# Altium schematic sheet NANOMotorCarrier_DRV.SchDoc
size A3
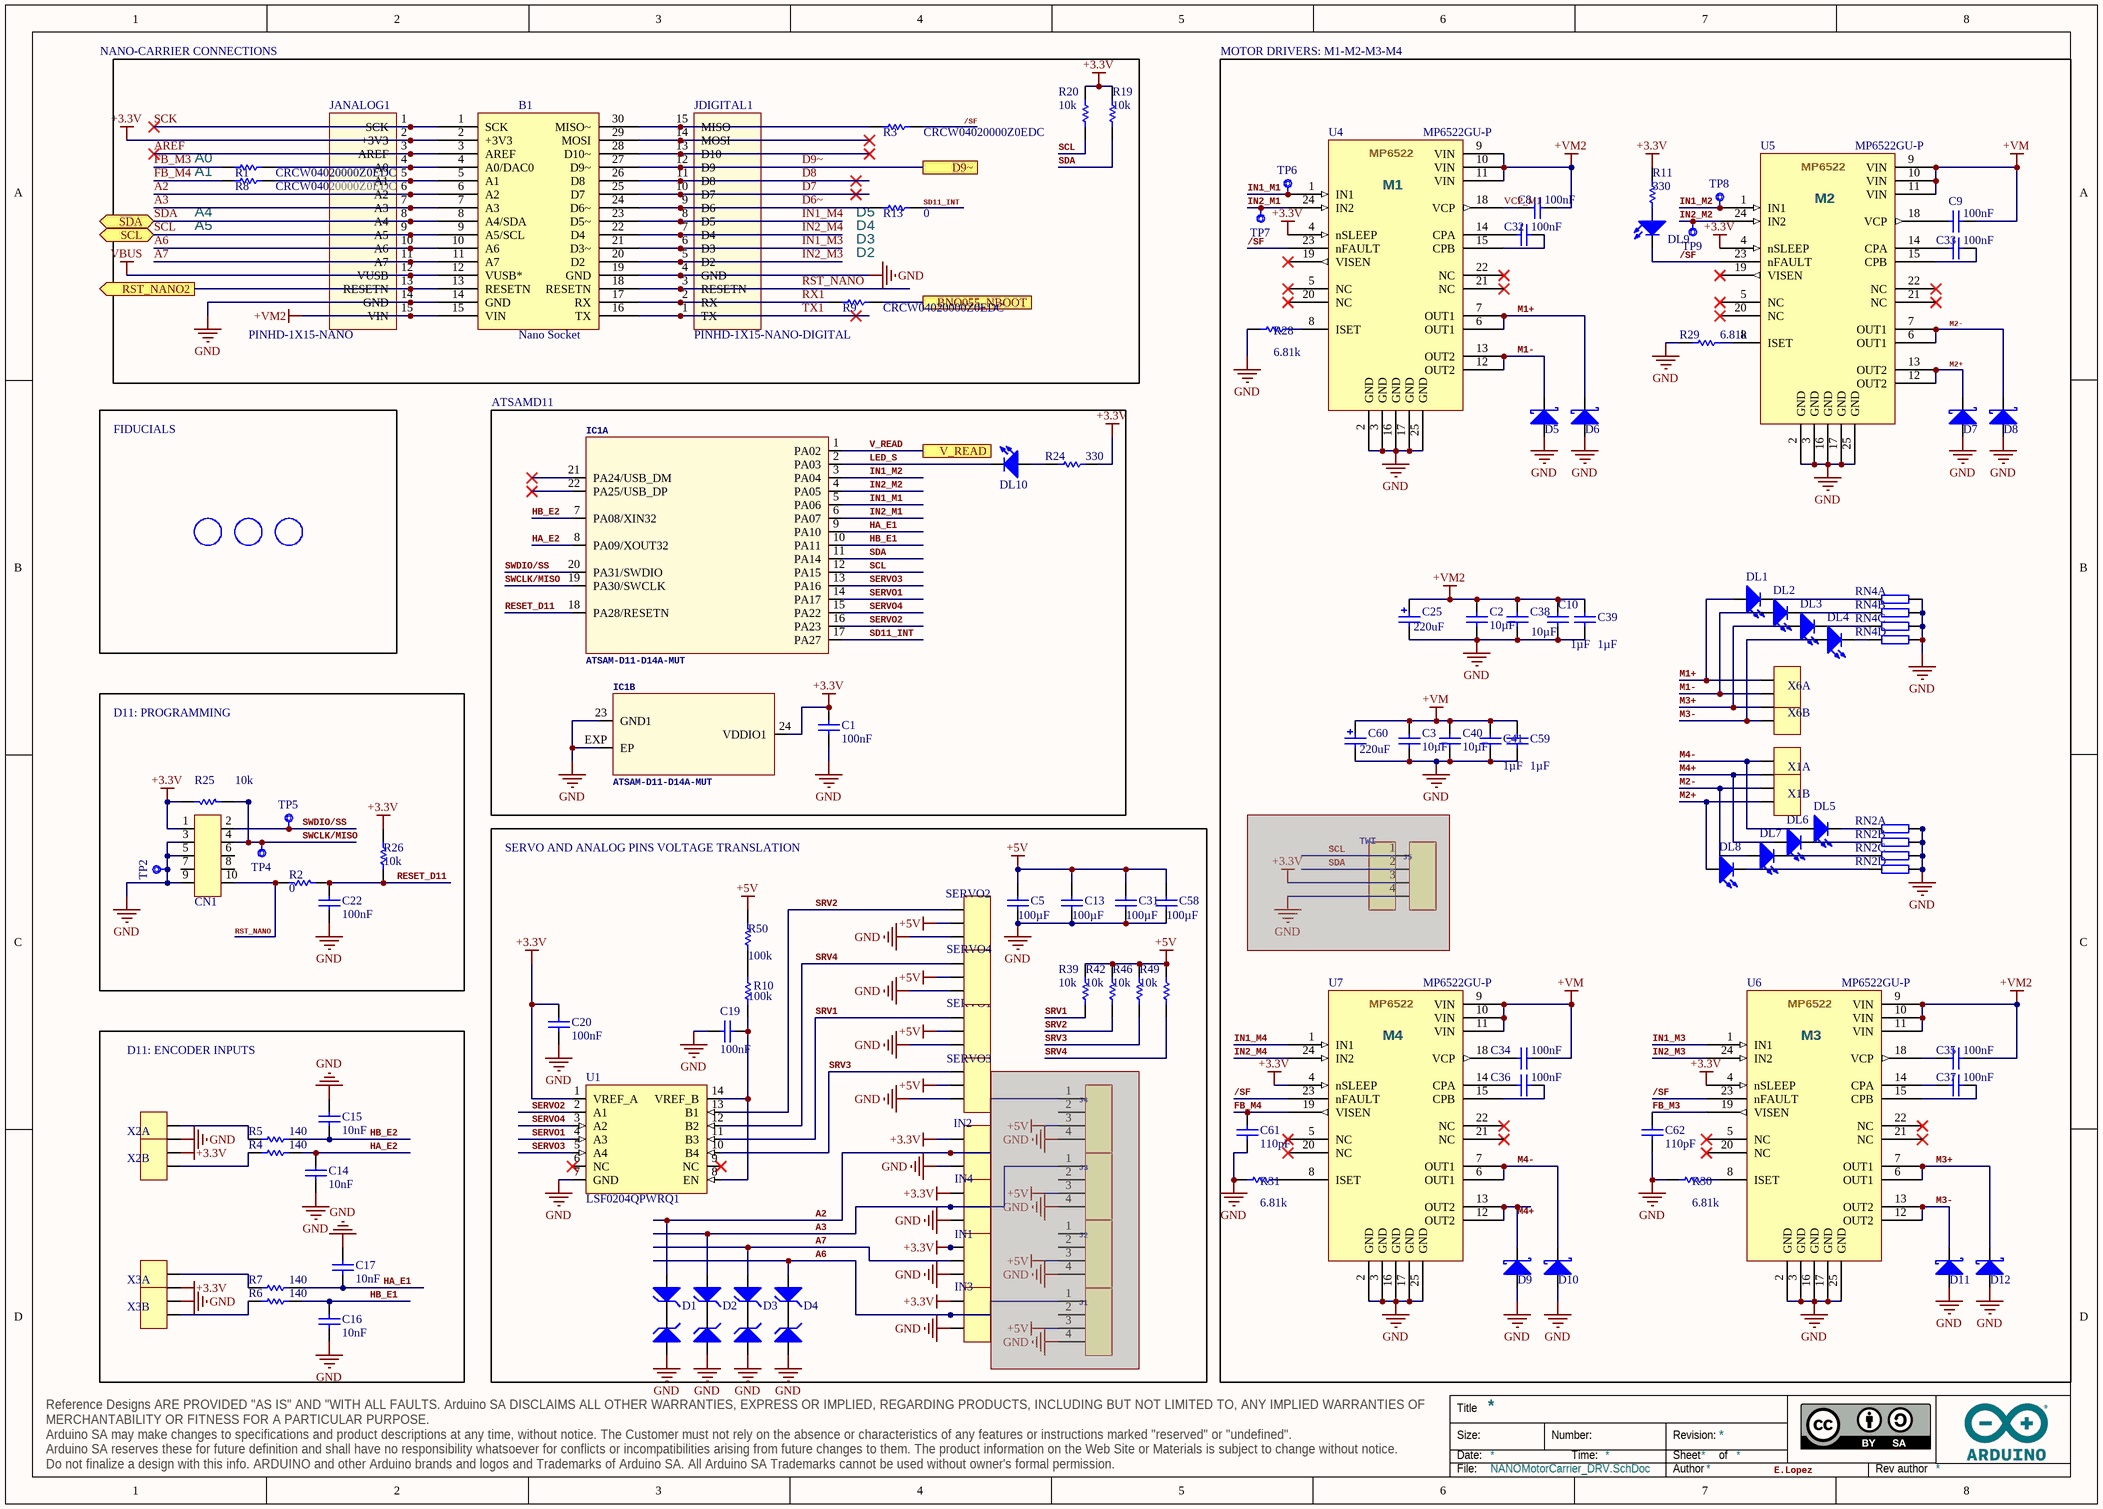
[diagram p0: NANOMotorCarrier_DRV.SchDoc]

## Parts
B1  Nano Socket  [Nano Socket-Footprint-1]
C1  value 100nF  [CAP-0402]  (hidden comment: GRM155R61H104KE19D)
C2  value 10µF  [CAP-1206]  (hidden comment: GRM31CR61H106KA12L)
C3  value 10µF  [CAP-1206]  (hidden comment: GRM31CR61H106KA12L)
C5  value 100µF  [CAP-1206]  (hidden comment: CL31A107MPHNNNE)
C8  value 100nF  [CAP-0402]  (hidden comment: GRM155R61H104KE19D)
C9  value 100nF  [CAP-0402]  (hidden comment: GRM155R61H104KE19D)
C10  value 1µF  [CAP-0603]  (hidden comment: C0603C105K3PACTU)
C13  value 100µF  [CAP-1206]  (hidden comment: CL31A107MPHNNNE)
C14  value 10nF  [CAP-0402]  (hidden comment: C0402C103K5RACTU)
C15  value 10nF  [CAP-0402]  (hidden comment: C0402C103K5RACTU)
C16  value 10nF  [CAP-0402]  (hidden comment: C0402C103K5RACTU)
C17  value 10nF  [CAP-0402]  (hidden comment: C0402C103K5RACTU)
C19  value 100nF  [CAP-0402]  (hidden comment: GRM155R61H104KE19D)
C20  value 100nF  [CAP-0402]  (hidden comment: GRM155R61H104KE19D)
C22  value 100nF  [CAP-0402]  (hidden comment: GRM155R61H104KE19D)
C25  Capacitance: 220uF  [CAPAE7866X80L]  (hidden comment: EEEFTE221XAP)
C31  value 100µF  [CAP-1206]  (hidden comment: CL31A107MPHNNNE)
C32  value 100nF  [CAP-0402]  (hidden comment: GRM155R61H104KE19D)
C33  value 100nF  [CAP-0402]  (hidden comment: GRM155R61H104KE19D)
C34  value 100nF  [CAP-0402]  (hidden comment: GRM155R61H104KE19D)
C35  value 100nF  [CAP-0402]  (hidden comment: GRM155R61H104KE19D)
C36  value 100nF  [CAP-0402]  (hidden comment: GRM155R61H104KE19D)
C37  value 100nF  [CAP-0402]  (hidden comment: GRM155R61H104KE19D)
C38  value 10µF  [CAP-1206]  (hidden comment: GRM31CR61H106KA12L)
C39  value 1µF  [CAP-0603]  (hidden comment: C0603C105K3PACTU)
C40  value 10µF  [CAP-1206]  (hidden comment: GRM31CR61H106KA12L)
C41  value 1µF  [CAP-0603]  (hidden comment: C0603C105K3PACTU)
C58  value 100µF  [CAP-1206]  (hidden comment: CL31A107MPHNNNE)
C59  value 1µF  [CAP-0603]  (hidden comment: C0603C105K3PACTU)
C60  Capacitance: 220uF  [CAPAE7866X80L]  (hidden comment: EEEFTE221XAP)
C61  value 110pF  [CAP-0402]  (hidden comment: GRM1555C1H111JA01D)
C62  value 110pF  [CAP-0402]  (hidden comment: GRM1555C1H111JA01D)
CN1  HPH2-A-10-SGA  [PINHEAD_2X05_127]  (value not drawn)
D1  DESD3V3S1BL-7B  [X1-DFN1006-2]  (value not drawn)
D2  DESD3V3S1BL-7B  [X1-DFN1006-2]  (value not drawn)
D3  DESD3V3S1BL-7B  [X1-DFN1006-2]  (value not drawn)
D4  DESD3V3S1BL-7B  [X1-DFN1006-2]  (value not drawn)
D5  PMEG6020AELRX  [SOD123-1]  (value not drawn)
D6  PMEG6020AELRX  [SOD123-1]  (value not drawn)
D7  PMEG6020AELRX  [SOD123-1]  (value not drawn)
D8  PMEG6020AELRX  [SOD123-1]  (value not drawn)
D9  PMEG6020AELRX  [SOD123-1]  (value not drawn)
D10  PMEG6020AELRX  [SOD123-1]  (value not drawn)
D11  PMEG6020AELRX  [SOD123-1]  (value not drawn)
D12  PMEG6020AELRX  [SOD123-1]  (value not drawn)
DL1  KPT-1608YC  [LEDC1608X80N-AK]  (value not drawn)
DL2  KPT-1608YC  [LEDC1608X80N-AK]  (value not drawn)
DL3  KPT-1608YC  [LEDC1608X80N-AK]  (value not drawn)
DL4  KPT-1608YC  [LEDC1608X80N-AK]  (value not drawn)
DL5  KPT-1608YC  [LEDC1608X80N-AK]  (value not drawn)
DL6  KPT-1608YC  [LEDC1608X80N-AK]  (value not drawn)
DL7  KPT-1608YC  [LEDC1608X80N-AK]  (value not drawn)
DL8  KPT-1608YC  [LEDC1608X80N-AK]  (value not drawn)
DL9  KPT-1608SECK  [LEDC1608X80N-AK]  (value not drawn)
DL10  KPT-1608SECK  [LEDC1608X80N-AK]  (value not drawn)
fid1  Fiducial mark 1.5mm  [FIDUCIAL-1.5]  (value not drawn)  (no BOM)
fid2  Fiducial mark 1.5mm  [FIDUCIAL-1.5]  (value not drawn)  (no BOM)
fid3  Fiducial mark 1.5mm  [FIDUCIAL-1.5]  (value not drawn)  (no BOM)
IC1  ATSAM-D11-D14A-MUT  [VQFN24]  (parts A,B of 2)
IN1  LHA-03-TS  [MODULINO-3]  (value not drawn)
IN2  LHA-03-TS  [MODULINO-3]  (value not drawn)
IN3  LHA-03-TS  [MODULINO-3]  (value not drawn)
IN4  LHA-03-TS  [MODULINO-3]  (value not drawn)
J1  110990030  [HW4-2.0]  (value not drawn)  (masked out: inside a compile mask, not in the netlist)
J2  110990030  [HW4-2.0]  (value not drawn)  (masked out: inside a compile mask, not in the netlist)
J3  110990030  [HW4-2.0]  (value not drawn)  (masked out: inside a compile mask, not in the netlist)
J4  110990030  [HW4-2.0]  (value not drawn)  (masked out: inside a compile mask, not in the netlist)
J5  110990030  [HW4-2.0]  (value not drawn)  (masked out: inside a compile mask, not in the netlist)
JANALOG1  PINHD-1X15-NANO  [New footprint 1]
JDIGITAL1  PINHD-1X15-NANO-DIGITAL  [PINHD-1X14_5VF]
R1  CRCW04020000Z0EDC  [RES-0402]
R2  value 0  [RES-0402]  (hidden comment: CRCW04020000Z0EDC)
R3  CRCW04020000Z0EDC  [RES-0402]
R4  value 140  [RES-0402]  (hidden comment: CRCW0402140RFKED)
R5  value 140  [RES-0402]  (hidden comment: CRCW0402140RFKED)
R6  value 140  [RES-0402]  (hidden comment: CRCW0402140RFKED)
R7  value 140  [RES-0402]  (hidden comment: CRCW0402140RFKED)
R8  CRCW04020000Z0EDC  [RES-0402]
R9  CRCW04020000Z0EDC  [RES-0402]
R10  value 100k  [RES-0402]  (hidden comment: CRCW0402100KFKEDC)
R11  value 330  [RES-0402]  (hidden comment: CRCW0402330RJNED)
R13  value 0  [RES-0402]  (hidden comment: CRCW04020000Z0EDC)
R19  value 10k  [RES-0402]  (hidden comment: CRCW040210K0FKED)
R20  value 10k  [RES-0402]  (hidden comment: CRCW040210K0FKED)
R24  value 330  [RES-0402]  (hidden comment: CRCW0402330RJNED)
R25  value 10k  [RES-0402]  (hidden comment: CRCW040210K0FKED)
R26  value 10k  [RES-0402]  (hidden comment: CRCW040210K0FKED)
R28  value 6.81k  [RES-0402]  (hidden comment: CRCW04026K81FKED)
R29  value 6.81k  [RES-0402]  (hidden comment: CRCW04026K81FKED)
R30  value 6.81k  [RES-0402]  (hidden comment: CRCW04026K81FKED)
R31  value 6.81k  [RES-0402]  (hidden comment: CRCW04026K81FKED)
R39  value 10k  [RES-0402]  (hidden comment: CRCW040210K0FKED)
R42  value 10k  [RES-0402]  (hidden comment: CRCW040210K0FKED)
R46  value 10k  [RES-0402]  (hidden comment: CRCW040210K0FKED)
R49  value 10k  [RES-0402]  (hidden comment: CRCW040210K0FKED)
R50  value 100k  [RES-0402]  (hidden comment: CRCW0402100KFKEDC)
RN2  CAY16-102J4LF  [CAY16]  (value not drawn)  (parts A,B,C,D of 4)
RN4  CAY16-102J4LF  [CAY16]  (value not drawn)  (parts A,B,C,D of 4)
SERVO1  LHA-03-TS-OUT  [LHA-03-TS-OUT-Footprint-1]  (value not drawn)
SERVO2  LHA-03-TS-OUT  [LHA-03-TS-OUT-Footprint-1]  (value not drawn)
SERVO3  LHA-03-TS-OUT  [LHA-03-TS-OUT-Footprint-1]  (value not drawn)
SERVO4  LHA-03-TS-OUT  [LHA-03-TS-OUT-Footprint-1]  (value not drawn)
TP2  CMP-018-0006-A.4  [TP-1.27MM]  (value not drawn)  (no BOM)
TP4  CMP-018-0006-A.4  [TP-1.27MM]  (value not drawn)  (no BOM)
TP5  CMP-018-0006-A.4  [TP-1.27MM]  (value not drawn)  (no BOM)
TP6  CMP-018-0006-A.4  [TP-1.27MM]  (value not drawn)  (no BOM)
TP7  CMP-018-0006-A.4  [TP-1.27MM]  (value not drawn)  (no BOM)
TP8  CMP-018-0006-A.4  [TP-1.27MM]  (value not drawn)  (no BOM)
TP9  CMP-018-0006-A.4  [TP-1.27MM]  (value not drawn)  (no BOM)
TWI  LHA-04-TS  [MODULINO-4]  (value not drawn)  (masked out: inside a compile mask, not in the netlist)
U1  LSF0204QPWRQ1  [TSOP65P640X120-14L]
U4  MP6522GU-P  [QFN65P500X500X100_HS-25N]
U5  MP6522GU-P  [QFN65P500X500X100_HS-25N]
U6  MP6522GU-P  [QFN65P500X500X100_HS-25N]
U7  MP6522GU-P  [QFN65P500X500X100_HS-25N]
X1A  MK125002GO  [MK125002GO]  (value not drawn)
X1B  MK125002GO  [MK125002GO]  (value not drawn)
X2A  MK125002GO  [MK125002GO]  (value not drawn)
X2B  MK125002GO  [MK125002GO]  (value not drawn)
X3A  MK125002GO  [MK125002GO]  (value not drawn)
X3B  MK125002GO  [MK125002GO]  (value not drawn)
X6A  MK125002GO  [MK125002GO]  (value not drawn)
X6B  MK125002GO  [MK125002GO]  (value not drawn)

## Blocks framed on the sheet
FIDUCIALS: fid1-fid3
ATSAMD11: C1 DL10 IC1 R24
D11: PROGRAMMING: C22 CN1 R2 R25 R26 TP2 TP4 TP5
SERVO AND ANALOG PINS VOLTAGE TRANSLATION: C5 C13 C19 C20 C31 C58 D1-D4 IN1-IN4 J1-J4 R10 R39 R42 R46 R49 R50 SERVO1-SERVO4 U1
D11: ENCODER INPUTS: C14-C17 R4-R7 X2A X2B X3A X3B

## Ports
BNO055_NBOOT, D9~, RST_NANO2 (out), SCL (bidir), SDA (bidir), V_READ

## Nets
+3.3V: B1.2(+3V3) C1.2 C20.2 CN1.1 IC1.24(VDDIO1) IN1.1 IN2.1 IN3.1 IN4.1 JANALOG1.2(+3V3) R11.1 R19.2 R20.2 R24.1 R25.1 R26.1 U1.1(VREF_A) U4.4(nSLEEP) U5.4(nSLEEP) U6.4(nSLEEP) U7.4(nSLEEP) X2B.2 X3A.1
+5V: C5.2 C13.2 C31.2 C58.2 R39.2 R42.2 R46.2 R49.2 R50.2 SERVO1.2 SERVO2.2 SERVO3.2 SERVO4.2
+VM: C3.2 C9.2 C34.2 C40.2 C41.2 C59.2 C60.2 U5.9(VIN) U5.10(VIN) U5.11(VIN) U7.9(VIN) U7.10(VIN) U7.11(VIN)
+VM2: B1.15(VIN) C2.2 C8.2 C10.2 C25.2 C35.2 C38.2 C39.2 JANALOG1.15(VIN) U4.9(VIN) U4.10(VIN) U4.11(VIN) U6.9(VIN) U6.10(VIN) U6.11(VIN)
GND: B1.14(GND) B1.19(GND) C1.1 C2.1 C3.1 C5.1 C10.1 C13.1 C14.1 C15.2 C16.1 C17.2 C19.1 C20.1 C22.2 C25.1 C31.1 C38.1 C39.1 C40.1 C41.1 C58.1 C59.1 C60.1 C61.1 C62.1 CN1.3 CN1.5 CN1.9 D1.1 D2.1 D3.1 D4.1 D5.A D6.A D7.A D8.A D9.A D10.A D11.A D12.A IC1.23(GND1) IC1.EXP(EP) IN1.3 IN2.3 IN3.3 IN4.3 JANALOG1.14(GND) JDIGITAL1.4(GND) R28.1 R29.1 R30.1 R31.1 RN2.1 RN2.2 RN2.3 RN2.4 RN4.1 RN4.2 RN4.3 RN4.4 SERVO1.3 SERVO2.3 SERVO3.3 SERVO4.3 TP2.X U1.7(GND) U4.2(GND) U4.3(GND) U4.16(GND) U4.17(GND) U4.25(GND) U5.2(GND) U5.3(GND) U5.16(GND) U5.17(GND) U5.25(GND) U6.2(GND) U6.3(GND) U6.16(GND) U6.17(GND) U6.25(GND) U7.2(GND) U7.3(GND) U7.16(GND) U7.17(GND) U7.25(GND) X2A.1 X3B.2
VBUS: B1.12(VUSB*) JANALOG1.12(VUSB)
/SF: DL9.C R3.2 U4.23(nFAULT) U5.23(nFAULT) U6.23(nFAULT) U7.23(nFAULT)
A2: B1.6(A2) D1.2 IN2.2 JANALOG1.6(A2)
A3: B1.7(A3) D2.2 IN4.2 JANALOG1.7(A3)
A6: B1.10(A6) D4.2 IN3.2 JANALOG1.10(A6)
A7: B1.11(A7) D3.2 IN1.2 JANALOG1.11(A7)
AREF: B1.3(AREF) JANALOG1.3(AREF)
BNO055_NBOOT: R9.2 ; port BNO055_NBOOT
D6~: B1.24(D6~) JDIGITAL1.9(D6) R13.1
D7: B1.25(D7) JDIGITAL1.10(D7)
D8: B1.26(D8) JDIGITAL1.11(D8)
D9~: B1.27(D9~) JDIGITAL1.12(D9) ; port D9~
FB_M3: C62.2 R1.1 U6.19(VISEN)
FB_M4: C61.2 R8.1 U7.19(VISEN)
HA_E1: C17.1 IC1.9(PA10) R7.1
HA_E2: C14.2 IC1.8(PA09/XOUT32) R4.1
HB_E1: C16.2 IC1.10(PA11) R6.1
HB_E2: C15.1 IC1.7(PA08/XIN32) R5.1
IN1_M1: IC1.5(PA06) TP6.X U4.1(IN1)
IN1_M2: IC1.3(PA04) TP8.X U5.1(IN1)
IN1_M3: B1.21(D3~) JDIGITAL1.6(D3) U6.1(IN1)
IN1_M4: B1.23(D5~) JDIGITAL1.8(D5) U7.1(IN1)
IN2_M1: IC1.6(PA07) TP7.X U4.24(IN2)
IN2_M2: IC1.4(PA05) TP9.X U5.24(IN2)
IN2_M3: B1.20(D2) JDIGITAL1.5(D2) U6.24(IN2)
IN2_M4: B1.22(D4) JDIGITAL1.7(D4) U7.24(IN2)
LED_S: DL10.C IC1.2(PA03)
M1+: D6.C DL1.A U4.6(OUT1) U4.7(OUT1) X6A.1
M1-: D5.C DL2.A U4.12(OUT2) U4.13(OUT2) X6A.2
M2+: D7.C DL8.A U5.12(OUT2) U5.13(OUT2) X1B.2
M2-: D8.C DL7.A U5.6(OUT1) U5.7(OUT1) X1B.1
M3+: D12.C DL3.A U6.6(OUT1) U6.7(OUT1) X6B.1
M3-: D11.C DL4.A U6.12(OUT2) U6.13(OUT2) X6B.2
M4+: D9.C DL6.A U7.12(OUT2) U7.13(OUT2) X1A.2
M4-: D10.C DL5.A U7.6(OUT1) U7.7(OUT1) X1A.1
RESET_D11: C22.1 IC1.18(PA28/RESETN) R2.1 R26.2
RST_NANO: B1.18(RESETN) CN1.10 JDIGITAL1.3(RESETN) R2.2
RST_NANO2: B1.13(RESETN) JANALOG1.13(RESETN) ; port RST_NANO2
RX1: B1.17(RX) JDIGITAL1.2(RX) R9.1
SCK: B1.1(SCK) JANALOG1.1(SCK)
SCL: B1.9(A5/SCL) IC1.12(PA15) JANALOG1.9(A5) R20.1 ; port SCL
SD11_INT: IC1.17(PA27) R13.2
SDA: B1.8(A4/SDA) IC1.11(PA14) JANALOG1.8(A4) R19.1 ; port SDA
SERVO1: IC1.14(PA17) U1.4(A3)
SERVO2: IC1.16(PA23) U1.2(A1)
SERVO3: IC1.13(PA16) U1.5(A4)
SERVO4: IC1.15(PA22) U1.3(A2)
SRV1: R39.1 SERVO1.1 U1.11(B3)
SRV2: R42.1 SERVO2.1 U1.13(B1)
SRV3: R46.1 SERVO3.1 U1.10(B4)
SRV4: R49.1 SERVO4.1 U1.12(B2)
SWCLK/MISO: CN1.4 IC1.19(PA30/SWCLK) R25.2 TP4.X
SWDIO/SS: CN1.2 IC1.20(PA31/SWDIO) TP5.X
TX1: B1.16(TX) JDIGITAL1.1(TX)
V_READ: IC1.1(PA02) ; port V_READ
VCP_M1: C8.1 U4.18(VCP)
NetB1_4: B1.4(A0/DAC0) JANALOG1.4(A0) R1.2
NetB1_5: B1.5(A1) JANALOG1.5(A1) R8.2
NetB1_28: B1.28(D10~) JDIGITAL1.13(D10)
NetB1_29: B1.29(MOSI) JDIGITAL1.14(MOSI)
NetB1_30: B1.30(MISO~) JDIGITAL1.15(MISO) R3.1
NetC9_1: C9.1 U5.18(VCP)
NetC19_2: C19.2 R10.1 U1.8(EN) U1.14(VREF_B)
NetC32_1: C32.1 U4.14(CPA)
NetC32_2: C32.2 U4.15(CPB)
NetC33_1: C33.1 U5.14(CPA)
NetC33_2: C33.2 U5.15(CPB)
NetC34_1: C34.1 U7.18(VCP)
NetC35_1: C35.1 U6.18(VCP)
NetC36_1: C36.1 U7.14(CPA)
NetC36_2: C36.2 U7.15(CPB)
NetC37_1: C37.1 U6.14(CPA)
NetC37_2: C37.2 U6.15(CPB)
NetDL1_C: DL1.C RN4.8
NetDL2_C: DL2.C RN4.7
NetDL3_C: DL3.C RN4.6
NetDL4_C: DL4.C RN4.5
NetDL5_C: DL5.C RN2.8
NetDL6_C: DL6.C RN2.7
NetDL7_C: DL7.C RN2.6
NetDL8_C: DL8.C RN2.5
NetDL9_A: DL9.A R11.2
NetDL10_A: DL10.A R24.2
NetR4_2: R4.2 X2B.1
NetR5_2: R5.2 X2A.2
NetR6_2: R6.2 X3B.1
NetR7_2: R7.2 X3A.2
NetR10_2: R10.2 R50.1
NetR28_2: R28.2 U4.8(ISET)
NetR29_2: R29.2 U5.8(ISET)
NetR30_2: R30.2 U6.8(ISET)
NetR31_2: R31.2 U7.8(ISET)

Not connected (* = marked no-connect by the designer): CN1 6 7 8; IC1 21(PA24/USB_DM)* 22(PA25/USB_DP)*; U1 6(NC)* 9(NC)*; U4 5(NC)* 19(VISEN)* 20(NC)* 21(NC)* 22(NC)*; U5 5(NC)* 19(VISEN)* 20(NC)* 21(NC)* 22(NC)*; U6 5(NC)* 20(NC)* 21(NC)* 22(NC)*; U7 5(NC)* 20(NC)* 21(NC)* 22(NC)*

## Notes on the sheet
- NANO-CARRIER CONNECTIONS
- MOTOR DRIVERS: M1-M2-M3-M4
- A0
- A1
- A4
- A5
- (near R13) D3
- (near R13) D4
- (near R13) D5
- (near U4) M1
- (near U5) M2
- D2
- (near U7) M4
- (near U6) M3
- E.Lopez

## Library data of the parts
B1 = AF0003-A.2: Nano board socket + outline
C1 C8 C9 C19 C20 C22 C32-C37 = C0015-A.3: CAP CHIP 0402 100nF 50V X5R 10%; Manufacturer: Murata; Code Arduino: A5141
C2 C3 C38 C40 = C0061-A.3: CAP CHIP 1206 10uF 50V X5R 10%; Manufacturer: Murata; Code Arduino: 2227
C5 C13 C31 C58 = C0062-A.3: CAP CHIP 1206 100UF 10V X5R 20%; Manufacturer: Samsung; Code Arduino: A5503
C10 C39 C41 C59 = C0044-A.3: CAP CHIP 0603 1uF 25V X5R 10%; Manufacturer: KEMET; Code Arduino: 0006
C14-C17 = C0009-A.3: CAP CHIP 0402 10nF 50V X7R 10%; Manufacturer: KEMET; Code Arduino: 0165
C25 = C0090-A.3: CAP ALUM SMD 220uF 25V 20%; Manufacturer: Panasonic; Code Arduino: C0090; Life (Hours): 2000Hour; Ripple Current (AC): 600mA; ESR (Equivalent Series Resistance): 0.16; Leakage Current: 55uA; Dielectric Material: Aluminium; Lead Diameter: 0.65mm
C60 = C0090-A.3: CAP ALUM SMD 220uF 25V 20%; Manufacturer: Panasonic; Code Arduino: C0090; ESR (Equivalent Series Resistance): 0.16; Ripple Current: 600mA; Life (Hours): 2000Hour; Leakage Current: 55uA; Dielectric Material: Aluminium; Lead Diameter: 0.65mm
C61 C62 = C0021-A.3: CAP CHIP 0402 110pF 50V C0G 5%; Manufacturer: Murata; Code Arduino: 2264
CN1 = J0068-A.5: CONN CONN STRIP THD 1,27 M/2/D 10v AuF H6,3 JTAG; Manufacturer: Adam Tech; Code Arduino: 0171
D1-D4 = D0039-A.1: DIOEDE TVS ZENER 3.3V ESD PROTECTION; Manufacturer: Diodes Inc.; Code Arduino: D0039; Device Type: DIODE TVS ZENER; Direction: Bidirectional; Clamping Voltage: 7V; Max Reverse Leakage Current: 100nA; Number of Bidirectional Channels: 1; Max Power Dissipation: 35W; Min Breakdown Voltage: 3.8V; Breakdown Voltage: 6.5V; Element Configuration: Single; Peak Pulse Current: 5A; Power Line Protection: No
D5-D12 = D0026-A.2: DIODE SCHOTTKY SMD 1A 40V SOD123FL; Manufacturer: Nexperia; Code Arduino: 2208
DL1-DL8 = L0008-A.3: LED SMD 0603 GIA588   8mcd 120^; Manufacturer: Kingbright; Code Arduino: 2243
DL9 DL10 = L0006-A.3: LED SMD 0603 ORANGE601 250mcd 120^; Manufacturer: Kingbright; Code Arduino: 2207
fid1-fid3 = UT0000-A.2
IC1 = U0040-A.2: IC ATSAM-D11-D14A-MUT; Manufacturer: Microchip
IN1-IN4 = J0021-A.2: CONN M.C.S. DIR BLC p2,54 3v; Manufacturer: Adam Tech; Code Arduino: 1695
J1-J5 = J0003-A.1: CONN GROVE EQUIV SMD 90 4POS; Manufacturer: Seeed; Code Arduino: 2240
JANALOG1 = J0055-A.4: CONN THD SOCKET F/1/D 15V JANALOG NANO-TYPE; Code Arduino: A5563
JDIGITAL1 = J0056-A.4: CONN THD SOCKET F/1/D 15V JDIGITAL NANO-TYPE; Code Arduino: A5564
R1 R3 R8 R9 = R0000-A.3: RES CHIP 0402 0R 1/16W; Manufacturer: Vishay; Value: 0; Power: 63mW; Tolerance: J; Code Arduino: 0039
R2 = R0000-A.3: RES CHIP 0402 0R 1/16W; Manufacturer: Vishay; Code Arduino: 0039; Tolerance: J; Power: 63mW
R4-R7 = R0021-A.3: RES CHIP 0402 140R 1% 1/16W; Manufacturer: Vishay; Code Arduino: 2234; Power: 63mW
R10 R50 = R0001-A.3: RES CHIP 0402 100K 1% 1/16W; Manufacturer: Vishay; Code Arduino: 0134; Power: 63mW
R11 = R0017-A.5: RES CHIP 0402 330R 5% 1/16W; Manufacturer: Vishay; Code Arduino: 2229; Power: 63mW
R13 = R0000-A.3: RES CHIP 0402 0R 1/16W; Manufacturer: Vishay; Power: 63mW; Tolerance: J; Code Arduino: 0039
R19 R20 R25 R26 R39 R42 R46 R49 = R0003-A.3: RES CHIP 0402 10K 1% 1/16W; Manufacturer: Vishay; Code Arduino: 0136; Power: 63mW
R24 = R0017-A.3: RES CHIP 0402 330R 5% 1/16W; Manufacturer: Vishay; Code Arduino: 2229; Power: 63mW
R28-R31 = R0030-A.3: RES CHIP 0402 6.81k 1% 1/16W; Manufacturer: Vishay; Code Arduino: A5341; Power: 63mW
RN2 RN4 = R0155-A.2: RES ARRAY 1206 4 RES 1K OHM; Manufacturer: Bourns; Code Arduino: 0005; Tolerance: 5%
SERVO1-SERVO4 = J0007-A.2: CONN M.C.S. DIR BLC p2,54 3v ORANGE; Manufacturer: Adam Tech; Code Arduino: 1696
TP2 TP4-TP9 = UT0014-A.2: Test point 1.27mm
TWI = J0008-A.1: CONN M.C.S. DIR BLC p2,54 4v; Manufacturer: Adam Tech; Code Arduino: 1693
U1 = U0111-A.2: IC LEVEL TRANSLATOR BIDIRECTIONAL 4BIT PUSH PULL; Manufacturer: Texas Instruments; Number of Bits: 4; Number of Circuits: 1; Code Arduino: U0111
U4-U7 = U0004-A.4: IC H BRIDGE MOTOR DRIVER 35V 3.2A; Manufacturer: MPS; Device Type: IC Motor Driver; Code Arduino: U0004
X1A X1B X2A X2B X3A X3B X6A X6B = J0012-A.4: CONN MORS.CS 2v p3,5 10A aLING.VER; Manufacturer: Adimpex; Code Arduino: 2341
